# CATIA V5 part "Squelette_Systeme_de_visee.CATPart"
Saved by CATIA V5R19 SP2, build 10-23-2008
Part number: Squelette_Arme
Bounding box of the stored display mesh (mm): x -50 to 50, y -600 to 200, z 1500 to 1500
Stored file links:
  G:\EU_thinkMotion\CFAO_2010\MMS_groupe2\MMS_groupe2\OK\nrosalie\nrosalie_cfao_support_d_arme_legere_final\Squelette_Systeme_de_visee.CATPart
  G:\EU_thinkMotion\CFAO_2010\MMS_groupe2\MMS_groupe2\OK\nrosalie\nrosalie_cfao_support_d_arme_legere_final\nrosalie_Support_d_arme_legere.CATProduct
  G:\EU_thinkMotion\CFAO_2010\MMS_groupe2\MMS_groupe2\OK\nrosalie\nrosalie_cfao_support_d_arme_legere_final\Squelette_Colone.CATPart
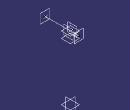
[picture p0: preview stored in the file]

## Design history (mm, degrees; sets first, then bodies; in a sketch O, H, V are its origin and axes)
External parameters (linked from other documents)
  External.Position_en_y_du_cou_du_servant = 300 mm
  External.Position_en_z_du_cou_du_servant = 100 mm
  External.Distance_centre_cou_servant_et_pivot_bras_support = 150 mm
  `External.Hauteur_viseur_de_l'arme` = 1500 mm
  External.Largeur_de_l_arme = 100 mm
  External.Longueur_de_l_arme = 700 mm
  External.Hauteur_de_l_arme = 150 mm
  External.Hauteur_colonne = 1250 mm
  `External.Position_en_-y_de_la_fixation_du_bras_du_canon_de_l'arme` = 600 mm
  `External.Ecartement_des_poignés_selon_l_axe_y` = 200 mm
  `External.Distance_viseur_centre_poignés` = 300 mm
  `External.Ecartement_des_poignés_selon_l_axe_x` = 70 mm
  External.Distance_minimale_selon_z_entre_dessous_arme_et_appui_inferieur_pres_de_la_colonne = 30 mm
  External.Distance_minimale_selon_y_de_appui_inferieur_pres_de_la_colonne_de_l_arme = 150 mm
  `External.Distance_selon_z_entre-centrage_arme_exterieur_axe_equilibrage_ext` = 50 mm
  External.Longueur_liaison_pivot_colonne_systeme = 150 mm
  External.Pourcentage_de_la_position_de_l_equilibrage_sur_la_piece_de_support_en_partant_axe_pivot_verticale = 10000 mm
Set1
  Plane1 "Plan_limite_inferieur_de_l_arme": type Offset, RefPlane Plane6, Offset 150 {= External.Hauteur_de_l_arme}, reversed
  Point1 "intersection_axe_colone_et_axe_viseur": (0, 0, 1500 {= `External.Hauteur_viseur_de_l'arme`})
  Line1: type PtDir, RefPoint Point1, Direction yz-plane, Start 50 {= External.Largeur_de_l_arme/2}, End -50 {= -External.Largeur_de_l_arme/2}
  Line2: type Normal, RefPoint Point1, RefSkin zx-plane, Start 600 {= External.Longueur_de_l_arme-100mm}, End -200
  Plane2 "Plan_limite_largeur_arme_en_x+": type Normal, Curve Line1, RefPoint vertex of Line1
  Plane3 "Plan_limite_largeur_arme_en_x-": type Normal, Curve Line1, RefPoint vertex of Line1
  Plane4 "Plan_limite_largeur_arme_en_y+": type Normal, Curve Line2, RefPoint vertex of Line2
  Plane5 "Plan_limite_largeur_corps_arme_en_y+": type Normal, Curve Line2, RefPoint vertex of Line2
  Plane6 "Plan_horizontal_median_viseur": type Normal, Curve Line3, RefPoint Point1
  Point2 "Position_croix_de_visée": type OnCurve, Support Line2, RefPoint vertex of Line2, Length 20
  Point3 "Position_premier_viseur": type OnCurve, Support Line2, RefPoint vertex of Line2, Length 70
Set2
  Point4 "Origine": linked copy from another document
  Plane7 "Plan_limite_superieur_colonne": linked copy from another document
  Line3 "Axe_vertical_colonne": linked copy from another document
  Point5 "Centre_plan_limite_superieur_colonne": linked copy from another document
Body1 (main body)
